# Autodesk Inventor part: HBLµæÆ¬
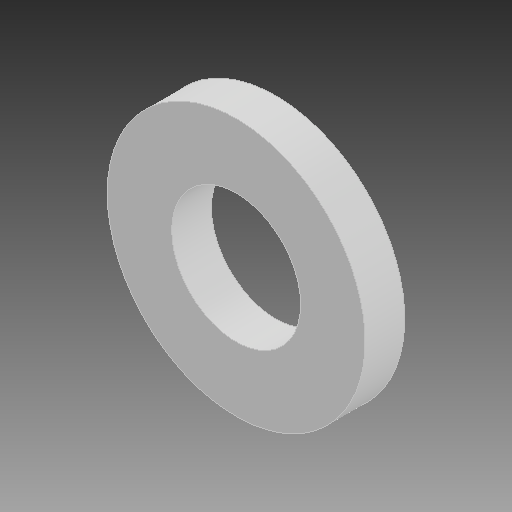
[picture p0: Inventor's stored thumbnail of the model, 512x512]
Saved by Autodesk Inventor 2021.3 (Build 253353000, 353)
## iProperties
Created: 2020-03
Part Number: HBLµæÆ¬
Material: Ogólny
Document SubType Name: Modeling
Designer: Przemyslaw Krecisz
Density: 1 g/cm^3
Appearance: Domyślna
Author: Przemyslaw Krecisz
Revision Number: ÈÎºÎ
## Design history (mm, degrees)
feature "Í¹Ì¨-À­Éì1"
node "Bryła1"
